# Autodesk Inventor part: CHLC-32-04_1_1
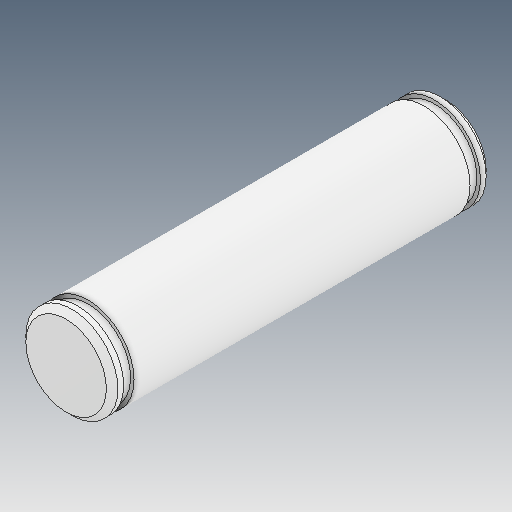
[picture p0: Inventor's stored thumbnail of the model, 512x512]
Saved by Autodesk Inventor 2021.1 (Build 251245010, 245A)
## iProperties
Created: 2021-05
Part Number: CHLC-32-04_1_1
Material: Ogólny
Document SubType Name: Modeling
Designer: user
Density: 1 g/cm^3
Appearance: Domyślna
Author: user
Revision Number: ÈÎºÎ
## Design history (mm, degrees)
feature "ÊäÈë1"
node "Bryła1"
